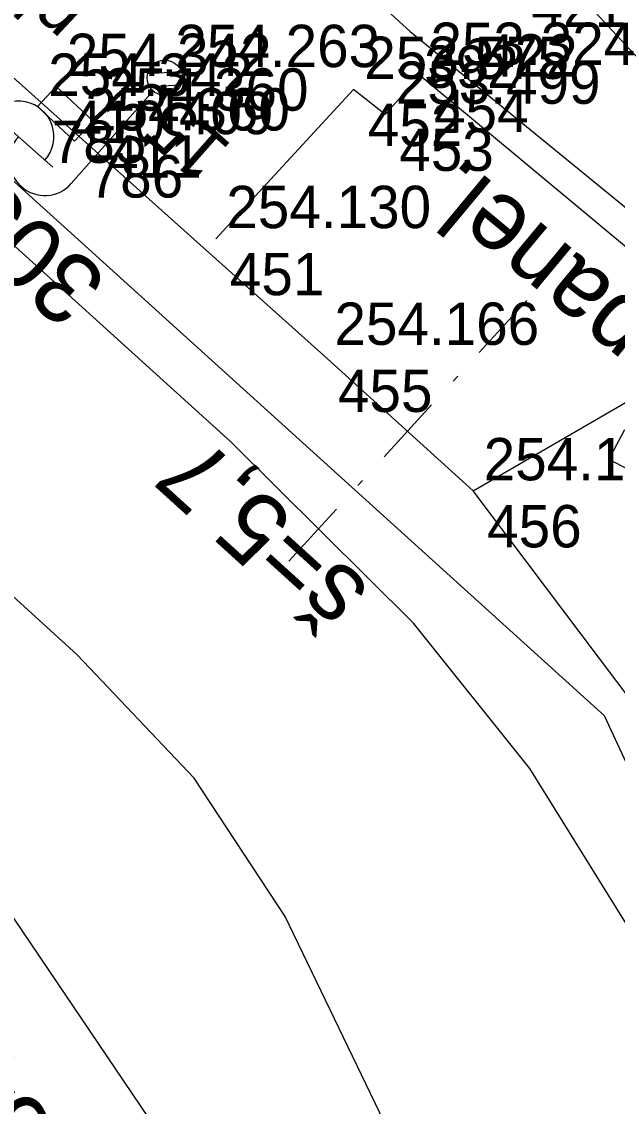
# Model space of a CAD drawing. Extents: x -496688 to -495455, y -1089309 to -1088026.
# Drawn here: x -496035.85 to -496018.98, y -1088663.71 to -1088632.98 of the extents above; entities that cross this region are included whole.
import ezdxf

# ---------------------------------------------------------------- set-up
doc = ezdxf.new("R2010")
doc.units = 0
for name, color, linetype in [('Vrstva 1', 7, 'Continuous'), ('Vrstva 16', 7, 'Continuous'), ('Vrstva 17', 7, 'Continuous'), ('Vrstva 23', 7, 'Continuous'), ('Vrstva 25', 7, 'Continuous'), ('Vrstva 36', 7, 'Continuous'), ('Vrstva 47', 7, 'Continuous'), ('Vrstva 53', 7, 'Continuous'), ('Vrstva 55', 7, 'Continuous'), ('Vrstva 57', 7, 'Continuous'), ('Vrstva 60', 7, 'Continuous'), ('Vrstva 61', 7, 'Continuous')]:
    doc.layers.add(name, color=color, linetype=linetype)

msp = doc.modelspace()

# ---------------------------------------------------------------- linework, layer by layer
at = {"layer": 'Vrstva 1'}
msp.add_lwpolyline([(-496044.162, -1088615.65), (-496024.853, -1088633.259), (-496017.591, -1088639.193), (-496010.937, -1088644.43)], dxfattribs=at)
at = {"layer": 'Vrstva 16'}
for points in [[(-496011.139, -1088641.838), (-496021.943, -1088630.19), (-496026.746, -1088625.404), (-496025.744, -1088623.192), (-496020.927, -1088627.681), (-496019.016, -1088629.263), (-496009.248, -1088640.851), (-496011.139, -1088641.838)], [(-496023.067, -1088646.276), (-496018.506, -1088643.628), (-496015.378, -1088646.173), (-496013.479, -1088643.743), (-496024.573, -1088634.51), (-496025.557, -1088635.61), (-496026.449, -1088634.906), (-496030.356, -1088639.132)]]:
    msp.add_lwpolyline(points, dxfattribs=at)
at = {"layer": 'Vrstva 17'}
for p, q in [((-496022.892, -1088642.356), (-496021.543, -1088640.879)), ((-496023.633, -1088643.168), (-496023.499, -1088643.021)), ((-496025.588, -1088645.31), (-496024.24, -1088643.834)), ((-496026.329, -1088646.123), (-496026.195, -1088645.976)), ((-496028.285, -1088648.265), (-496026.936, -1088646.788))]:
    msp.add_line(p, q, dxfattribs=at)
msp.add_lwpolyline([(-496008.397, -1088665.951), (-496014.409, -1088657.761), (-496023.067, -1088646.276), (-496027.294, -1088642.439), (-496042.866, -1088628.504), (-496063.314, -1088610.129), (-496090.785, -1088585.443), (-496123.862, -1088555.707), (-496127.206, -1088552.748), (-496136.794, -1088544.006), (-496152.301, -1088530.524)], dxfattribs=at)
at = {"layer": 'Vrstva 23'}
msp.add_lwpolyline([(-496016.46, -1088645.695), (-496016.914, -1088646.553), (-496019.222, -1088645.39), (-496018.768, -1088644.532)], dxfattribs=at)
at = {"layer": 'Vrstva 25'}
for p, q in [((-496031.332, -1088634.402), (-496032.287, -1088634.461)), ((-496032.131, -1088634.946), (-496034.448, -1088637.569)), ((-496031.345, -1088634.778), (-496032.223, -1088634.832)), ((-496034.973, -1088637.105), (-496036.921, -1088635.384))]:
    msp.add_line(p, q, dxfattribs=at)
msp.add_circle((-496031.8, -1088634.571), 0.5, dxfattribs=at)
msp.add_circle((-496031.8, -1088634.571), 0.5, dxfattribs=at)
for centre, start, end in [((-496035.939, -1088636.236), 317.8409, 139.246), ((-496035.198, -1088636.907), 138.5435, 318.5435)]:
    msp.add_arc(centre, 1, start, end, dxfattribs=at)
at = {"layer": 'Vrstva 47'}
msp.add_lwpolyline([(-496035.401, -1088635.385), (-496034.874, -1088634.823), (-496033.828, -1088635.804), (-496034.355, -1088636.366), (-496035.401, -1088635.385)], dxfattribs=at)
at = {"layer": 'Vrstva 53'}
msp.add_lwpolyline([(-496006.16, -1088672.1), (-496009.66, -1088673.61), (-496019.34, -1088652.65), (-496125.77, -1088556.38), (-496187.85, -1088499.89), (-496224.3, -1088466.84), (-496274.7, -1088421.37), (-496308.3, -1088391.23), (-496341.24, -1088361.35), (-496344.49, -1088357.55), (-496352.49, -1088347.86), (-496352.14, -1088346.56), (-496371.02, -1088328.7), (-496406.7, -1088297.06), (-496406.34, -1088296.61), (-496407.86, -1088294.92), (-496408.29, -1088292.38), (-496407.56, -1088290.4), (-496405.24, -1088287.91)], dxfattribs=at)
at = {"layer": 'Vrstva 55'}
for p, q in [((-496126.78, -1088557.15), (-496029.94, -1088644.88)), ((-496125.29, -1088568.17), (-496034.28, -1088650.92)), ((-496024.75, -1088650.02), (-496029.94, -1088644.88)), ((-496021.46, -1088654.14), (-496024.75, -1088650.02)), ((-496030.97, -1088654.41), (-496034.28, -1088650.92)), ((-496040.52, -1088651.83), (-496031.57, -1088665.05)), ((-496016.84, -1088661.58), (-496021.46, -1088654.14)), ((-496028.39, -1088658.33), (-496030.97, -1088654.41)), ((-496024.31, -1088666.79), (-496028.39, -1088658.33))]:
    msp.add_line(p, q, dxfattribs=at)
at = {"layer": 'Vrstva 60'}
for p, q in [((-496024.853, -1088633.259), (-496024.853, -1088633.259)), ((-496024.853, -1088633.259), (-496024.853, -1088633.259)), ((-496031.8, -1088634.571), (-496031.8, -1088634.571)), ((-496031.8, -1088634.571), (-496031.8, -1088634.571)), ((-496024.573, -1088634.51), (-496024.573, -1088634.51)), ((-496024.573, -1088634.51), (-496024.573, -1088634.51)), ((-496034.874, -1088634.823), (-496034.874, -1088634.823)), ((-496034.874, -1088634.823), (-496034.874, -1088634.823)), ((-496026.449, -1088634.906), (-496026.449, -1088634.906)), ((-496026.449, -1088634.906), (-496026.449, -1088634.906)), ((-496035.401, -1088635.385), (-496035.401, -1088635.385)), ((-496035.401, -1088635.385), (-496035.401, -1088635.385)), ((-496025.557, -1088635.61), (-496025.557, -1088635.61)), ((-496025.557, -1088635.61), (-496025.557, -1088635.61)), ((-496033.828, -1088635.804), (-496033.828, -1088635.804)), ((-496033.828, -1088635.804), (-496033.828, -1088635.804)), ((-496034.355, -1088636.366), (-496034.355, -1088636.366)), ((-496034.355, -1088636.366), (-496034.355, -1088636.366)), ((-496030.356, -1088639.132), (-496030.356, -1088639.132)), ((-496030.356, -1088639.132), (-496030.356, -1088639.132)), ((-496027.294, -1088642.439), (-496027.294, -1088642.439)), ((-496027.294, -1088642.439), (-496027.294, -1088642.439)), ((-496019.222, -1088645.39), (-496019.222, -1088645.39)), ((-496019.222, -1088645.39), (-496019.222, -1088645.39)), ((-496023.067, -1088646.276), (-496023.067, -1088646.276)), ((-496023.067, -1088646.276), (-496023.067, -1088646.276)), ((-496019.34, -1088652.65), (-496019.34, -1088652.65)), ((-496019.34, -1088652.65), (-496019.34, -1088652.65))]:
    msp.add_line(p, q, dxfattribs=at)

# ---------------------------------------------------------------- texts
at = {"layer": 'Vrstva 16'}
msp.add_text('panel.', height=2, rotation=140.231, dxfattribs=at).set_placement((-496017.851, -1088641.406))
at = {"layer": 'Vrstva 17'}
msp.add_text('š=5,7', height=2, rotation=137.7689, dxfattribs=at).set_placement((-496025.933, -1088649.027))
at = {"layer": 'Vrstva 25'}
msp.add_text('15', height=1.5, rotation=138.5435, dxfattribs=at).set_placement((-496029.857, -1088636.515))
at = {"layer": 'Vrstva 36'}
msp.add_text('plyn', height=1.5, rotation=136.8367, dxfattribs=at).set_placement((-496033.966, -1088632.645))
at = {"layer": 'Vrstva 57'}
for s, rotation, p in [('3033/6', 138.4632, (-496033.341, -1088640.275)), ('2702/340', 118.9707, (-496031.646, -1088670.314))]:
    msp.add_text(s, height=2, rotation=rotation, dxfattribs=at).set_placement(p)
at = {"layer": 'Vrstva 60'}
for s, p in [('421', (-496021.411, -1088633.133)), ('421', (-496021.411, -1088633.133)), ('422', (-496022.782, -1088634.539)), ('422', (-496022.782, -1088634.539)), ('392', (-496024.453, -1088634.859)), ('392', (-496024.453, -1088634.859)), ('409', (-496031.4, -1088636.171)), ('409', (-496031.4, -1088636.171)), ('454', (-496024.173, -1088636.11)), ('454', (-496024.173, -1088636.11)), ('410', (-496034.474, -1088636.423)), ('410', (-496034.474, -1088636.423)), ('452', (-496026.049, -1088636.506)), ('452', (-496026.049, -1088636.506)), ('785', (-496035.001, -1088636.985)), ('785', (-496035.001, -1088636.985)), ('411', (-496033.428, -1088637.404)), ('411', (-496033.428, -1088637.404)), ('453', (-496025.157, -1088637.21)), ('453', (-496025.157, -1088637.21)), ('786', (-496033.955, -1088637.966)), ('786', (-496033.955, -1088637.966)), ('451', (-496029.956, -1088640.732)), ('451', (-496029.956, -1088640.732)), ('455', (-496026.894, -1088644.039)), ('455', (-496026.894, -1088644.039)), ('456', (-496022.667, -1088647.876)), ('456', (-496022.667, -1088647.876))]:
    msp.add_text(s, height=1.2, dxfattribs=at).set_placement(p)
at = {"layer": 'Vrstva 61'}
for s, p in [('254.263', (-496031.5, -1088634.271)), ('254.263', (-496031.5, -1088634.271)), ('253.324', (-496024.273, -1088634.21)), ('253.324', (-496024.273, -1088634.21)), ('254.342', (-496034.574, -1088634.523)), ('254.342', (-496034.574, -1088634.523)), ('253.575', (-496026.149, -1088634.606)), ('253.575', (-496026.149, -1088634.606)), ('254.342', (-496035.101, -1088635.085)), ('254.342', (-496035.101, -1088635.085)), ('254.360', (-496033.528, -1088635.504)), ('254.360', (-496033.528, -1088635.504)), ('253.499', (-496025.257, -1088635.31)), ('253.499', (-496025.257, -1088635.31)), ('254.360', (-496034.055, -1088636.066)), ('254.360', (-496034.055, -1088636.066)), ('254.130', (-496030.056, -1088638.832)), ('254.130', (-496030.056, -1088638.832)), ('254.166', (-496026.994, -1088642.139)), ('254.166', (-496026.994, -1088642.139)), ('254.117', (-496022.767, -1088645.976)), ('254.117', (-496022.767, -1088645.976))]:
    msp.add_text(s, height=1.2, dxfattribs=at).set_placement(p)

doc.saveas('drawing.dxf')
